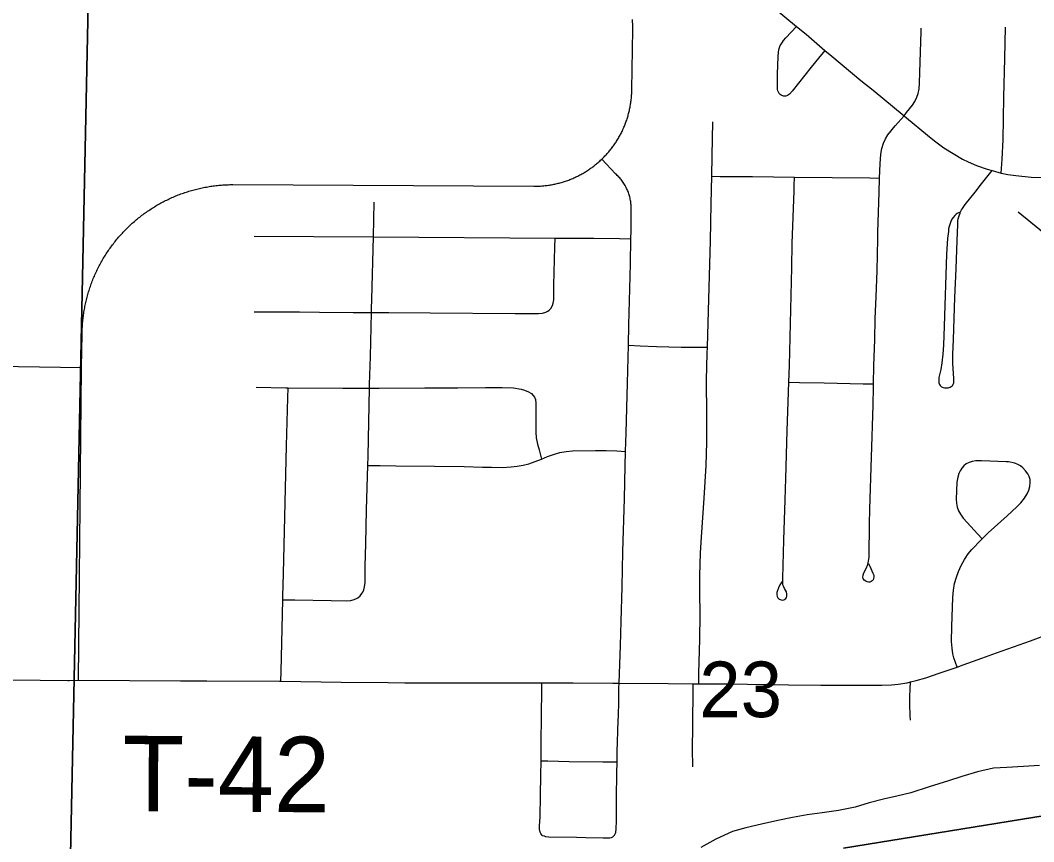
# Model space of a CAD drawing. Extents: x 0 to 34, y 0 to 22.
# Drawn here: x 5.405 to 6.168, y 18.807 to 19.426 of the extents above; entities that cross this region are included whole.
import ezdxf

# ---------------------------------------------------------------- set-up
doc = ezdxf.new("R2010")
doc.units = 0
for name, color, linetype in [('GM_X_City_Street', 7, 'Continuous'), ('GM_X_Major_River', 7, 'Continuous'), ('GM_X_Section', 7, 'Continuous'), ('GM_X_Section_Text', 7, 'Continuous'), ('GM_X_State_Route', 7, 'Continuous'), ('GM_X_Township_Road', 7, 'Continuous'), ('GM_X_Township_Road_Text', 7, 'Continuous')]:
    doc.layers.add(name, color=color, linetype=linetype)

msp = doc.modelspace()

# ---------------------------------------------------------------- linework, layer by layer
at = {"layer": 'GM_X_City_Street'}
msp.add_line((5.31011, 19.16656), (5.45108, 19.16403), dxfattribs=at)
for points in [[(5.4489, 18.92849), (5.45108, 19.16403), (5.45162, 19.18919), (5.45164, 19.19024), (5.45166, 19.19128), (5.4517, 19.19233), (5.45174, 19.19338), (5.4518, 19.19443), (5.45186, 19.19548), (5.45194, 19.19652), (5.45202, 19.19757), (5.45211, 19.19861), (5.45221, 19.19965), (5.45233, 19.2007), (5.45244, 19.20174), (5.45258, 19.20278), (5.45272, 19.20382), (5.45287, 19.20485), (5.45303, 19.20589), (5.4532, 19.20692), (5.45338, 19.20796), (5.45356, 19.20899), (5.45376, 19.21002), (5.45397, 19.21105), (5.45419, 19.21208), (5.45441, 19.2131), (5.45465, 19.21412), (5.45489, 19.21514), (5.45515, 19.21616), (5.45541, 19.21717), (5.45569, 19.21818), (5.45597, 19.21919), (5.45626, 19.2202), (5.45656, 19.2212), (5.45687, 19.2222), (5.45719, 19.2232), (5.45752, 19.2242), (5.45786, 19.22519), (5.4582, 19.22618), (5.45857, 19.22717), (5.45893, 19.22815), (5.4593, 19.22913), (5.45968, 19.23011), (5.46008, 19.23108), (5.46048, 19.23205), (5.46089, 19.23301), (5.46131, 19.23397), (5.46173, 19.23493), (5.46217, 19.23589), (5.46262, 19.23683), (5.46307, 19.23778), (5.46354, 19.23872), (5.464, 19.23966), (5.46449, 19.24059), (5.46497, 19.24152), (5.46547, 19.24244), (5.46598, 19.24335), (5.46649, 19.24427), (5.46701, 19.24518), (5.46754, 19.24608), (5.46808, 19.24698), (5.46863, 19.24788), (5.46918, 19.24877), (5.46975, 19.24965), (5.47032, 19.25053), (5.4709, 19.2514), (5.47149, 19.25227), (5.47209, 19.25314), (5.47269, 19.25399), (5.4733, 19.25484), (5.47392, 19.25569), (5.47455, 19.25653), (5.47518, 19.25737), (5.47582, 19.25819), (5.47647, 19.25901), (5.47713, 19.25983), (5.4778, 19.26064), (5.47847, 19.26145), (5.47915, 19.26224), (5.47983, 19.26303), (5.48053, 19.26382), (5.48123, 19.2646), (5.48194, 19.26537), (5.48266, 19.26614), (5.48338, 19.2669), (5.48411, 19.26765), (5.48485, 19.2684), (5.48559, 19.26914), (5.48634, 19.26987), (5.4871, 19.2706), (5.48786, 19.27131), (5.48863, 19.27202), (5.48941, 19.27273), (5.49019, 19.27342), (5.49098, 19.27411), (5.49178, 19.2748), (5.49258, 19.27547), (5.49339, 19.27614), (5.49421, 19.2768), (5.49503, 19.27745), (5.49585, 19.2781), (5.49669, 19.27874), (5.49753, 19.27936), (5.49836, 19.27998), (5.49922, 19.2806), (5.50007, 19.2812), (5.50093, 19.28181), (5.5018, 19.2824), (5.50267, 19.28297), (5.50355, 19.28355), (5.50443, 19.28412), (5.50532, 19.28468), (5.50621, 19.28522), (5.50711, 19.28576), (5.50801, 19.2863), (5.50892, 19.28683), (5.50983, 19.28734), (5.51075, 19.28785), (5.51167, 19.28835), (5.5126, 19.28884), (5.51353, 19.28932), (5.51446, 19.2898), (5.5154, 19.29026), (5.51635, 19.29072), (5.51729, 19.29117), (5.51825, 19.2916), (5.5192, 19.29203), (5.52016, 19.29246), (5.52112, 19.29287), (5.52209, 19.29328), (5.52306, 19.29367), (5.52404, 19.29406), (5.52501, 19.29443), (5.526, 19.2948), (5.52698, 19.29516), (5.52797, 19.29551), (5.52897, 19.29585), (5.52996, 19.29618), (5.53095, 19.29651), (5.53196, 19.29682), (5.53296, 19.29712), (5.53397, 19.29741), (5.53497, 19.2977), (5.53599, 19.29798), (5.537, 19.29825), (5.53802, 19.2985), (5.53904, 19.29875), (5.54006, 19.29899), (5.54108, 19.29922), (5.5421, 19.29944), (5.54313, 19.29965), (5.54416, 19.29985), (5.54519, 19.30004), (5.54622, 19.30022), (5.54726, 19.3004), (5.5483, 19.30056), (5.54933, 19.30071), (5.55037, 19.30086), (5.55141, 19.30099), (5.55245, 19.30112), (5.55349, 19.30123), (5.55454, 19.30133), (5.55558, 19.30143), (5.55662, 19.30152), (5.55767, 19.3016), (5.55872, 19.30166), (5.55976, 19.30172), (5.56081, 19.30177), (5.56186, 19.30181), (5.56291, 19.30183), (5.56396, 19.30185), (5.56501, 19.30186), (5.79187, 19.30063), (5.79271, 19.30063), (5.79355, 19.30065), (5.79438, 19.30066), (5.79522, 19.30069), (5.79605, 19.30073), (5.79688, 19.30078), (5.79772, 19.30084), (5.79855, 19.30091), (5.79939, 19.30098), (5.80022, 19.30107), (5.80105, 19.30116), (5.80188, 19.30127), (5.8027, 19.30138), (5.80353, 19.3015), (5.80436, 19.30164), (5.80518, 19.30178), (5.806, 19.30193), (5.80682, 19.30209), (5.80764, 19.30227), (5.80846, 19.30245), (5.80927, 19.30263), (5.81009, 19.30283), (5.81089, 19.30304), (5.8117, 19.30326), (5.8125, 19.30348), (5.81331, 19.30372), (5.81411, 19.30397), (5.8149, 19.30422), (5.8157, 19.30449), (5.81649, 19.30475), (5.81728, 19.30504), (5.81806, 19.30532), (5.81884, 19.30563), (5.81962, 19.30593), (5.82039, 19.30625), (5.82116, 19.30657), (5.82193, 19.30691), (5.82269, 19.30725), (5.82345, 19.3076), (5.8242, 19.30796), (5.82496, 19.30833), (5.8257, 19.30871), (5.82644, 19.3091), (5.82718, 19.30949), (5.82791, 19.30989), (5.82864, 19.31031), (5.82936, 19.31072), (5.83008, 19.31115), (5.8308, 19.31159), (5.83151, 19.31203), (5.83221, 19.31248), (5.8329, 19.31294), (5.8336, 19.31341), (5.83428, 19.31389), (5.83497, 19.31437), (5.83564, 19.31486), (5.83631, 19.31536), (5.83698, 19.31587), (5.83764, 19.31638), (5.83829, 19.31691), (5.83894, 19.31743), (5.83958, 19.31797), (5.84022, 19.31852), (5.84084, 19.31906), (5.84147, 19.31962), (5.84208, 19.32019), (5.84299, 19.32105), (5.8436, 19.32164), (5.84419, 19.32223), (5.84478, 19.32282), (5.84536, 19.32342), (5.84593, 19.32404), (5.84651, 19.32465), (5.84706, 19.32528), (5.84762, 19.32591), (5.84816, 19.32654), (5.8487, 19.32719), (5.84923, 19.32784), (5.84975, 19.3285), (5.85027, 19.32915), (5.85078, 19.32982), (5.85128, 19.3305), (5.85177, 19.33117), (5.85226, 19.33186), (5.85274, 19.33255), (5.85321, 19.33324), (5.85367, 19.33394), (5.85412, 19.33465), (5.85457, 19.33535), (5.85501, 19.33608), (5.85543, 19.33679), (5.85586, 19.33752), (5.85627, 19.33825), (5.85667, 19.33898), (5.85707, 19.33972), (5.85745, 19.34047), (5.85783, 19.34121), (5.85821, 19.34197), (5.85857, 19.34272), (5.85892, 19.34349), (5.85926, 19.34425), (5.8596, 19.34502), (5.85993, 19.34579), (5.86024, 19.34657), (5.86055, 19.34735), (5.86085, 19.34813), (5.86114, 19.34892), (5.86142, 19.34971), (5.8617, 19.3505), (5.86196, 19.3513), (5.86221, 19.35209), (5.86246, 19.3529), (5.8627, 19.3537), (5.86292, 19.35451), (5.86314, 19.35532), (5.86335, 19.35613), (5.86355, 19.35695), (5.86374, 19.35777), (5.86392, 19.35858), (5.86409, 19.35941), (5.86425, 19.36023), (5.86441, 19.36105), (5.86455, 19.36188), (5.86468, 19.36271), (5.8648, 19.36354), (5.86492, 19.36437), (5.86502, 19.3652), (5.86512, 19.36603), (5.8652, 19.36687), (5.86528, 19.3677), (5.86534, 19.36854), (5.8654, 19.36937), (5.86545, 19.37021), (5.86549, 19.37105), (5.86552, 19.37189), (5.86554, 19.37273), (5.86554, 19.37357), (5.86621, 19.41858), (5.86622, 19.41969), (5.86622, 19.4208), (5.86621, 19.42191), (5.8662, 19.42301), (5.86617, 19.42412), (5.86613, 19.42523), (5.86608, 19.42634)], [(6.01096, 19.40293), (6.00617, 19.39713), (6.00062, 19.39039), (5.98638, 19.37223), (5.98424, 19.36996), (5.98353, 19.3694), (5.9827, 19.36892), (5.98152, 19.36845), (5.9803, 19.36838), (5.97966, 19.36845), (5.97796, 19.36917), (5.97715, 19.36976), (5.97655, 19.37039), (5.97617, 19.37092), (5.9754, 19.37258), (5.97522, 19.37346), (5.97514, 19.37442), (5.97533, 19.38526), (5.97578, 19.39811), (5.97602, 19.40188), (5.97618, 19.40307), (5.97644, 19.40428), (5.97676, 19.40525), (5.97734, 19.4066), (5.97799, 19.40776), (5.97896, 19.40927), (5.97988, 19.41052), (5.98152, 19.41237), (5.98564, 19.41669), (5.98953, 19.42104)], [(6.07055, 19.35366), (6.07245, 19.35607), (6.07683, 19.36161), (6.07869, 19.36437), (6.08026, 19.36764), (6.08121, 19.37046), (6.0819, 19.37399), (6.08218, 19.37823), (6.08243, 19.38628), (6.08337, 19.4173), (6.08343, 19.41977)], [(6.14357, 19.31043), (6.14445, 19.32106), (6.1451, 19.33568), (6.14573, 19.36762), (6.14644, 19.39683), (6.14702, 19.42048)], [(6.04386, 19.01636), (6.04489, 19.0145), (6.04712, 19.00919), (6.04772, 19.00765), (6.04785, 19.00609), (6.04763, 19.0051), (6.0472, 19.00421), (6.04655, 19.00346), (6.04572, 19.00289), (6.04479, 19.00254), (6.04382, 19.00245), (6.04283, 19.00262), (6.04187, 19.00305), (6.04063, 19.004), (6.03986, 19.00523), (6.03963, 19.00622), (6.03972, 19.00777), (6.04023, 19.00938), (6.04191, 19.01264), (6.04321, 19.0156), (6.04389, 19.01813), (6.04424, 19.02134), (6.04436, 19.02948), (6.04449, 19.03876), (6.04459, 19.04623), (6.04483, 19.0574), (6.04742, 19.13563), (6.04754, 19.14932), (6.04759, 19.15169), (6.04784, 19.16544), (6.04858, 19.18529), (6.04892, 19.20082), (6.04961, 19.21757), (6.0502, 19.23683), (6.05077, 19.26105), (6.05093, 19.26352), (6.05087, 19.26601), (6.05169, 19.29583), (6.052, 19.30682), (6.05249, 19.31752), (6.05304, 19.32487), (6.05381, 19.32905), (6.05502, 19.3331), (6.05647, 19.33638), (6.0584, 19.33942), (6.06379, 19.34614), (6.07055, 19.35366)], [(5.91594, 18.92586), (5.91612, 18.93383), (5.91673, 18.95932), (5.91696, 18.97798), (5.91673, 18.99477), (5.91672, 19.00721), (5.9172, 19.02461), (5.91794, 19.0364), (5.92005, 19.06556), (5.92162, 19.09039), (5.92207, 19.10779), (5.92193, 19.12831), (5.92185, 19.15444), (5.92236, 19.17496), (5.92249, 19.17936), (5.92334, 19.20666), (5.92482, 19.2595), (5.92527, 19.28748), (5.92572, 19.30813), (5.92607, 19.32355), (5.92667, 19.34904)], [(5.86492, 19.26101), (5.86508, 19.26736), (5.86509, 19.28398), (5.86508, 19.28484), (5.86505, 19.28571), (5.865, 19.28657), (5.86492, 19.28743), (5.86482, 19.28829), (5.86471, 19.28915), (5.86457, 19.29), (5.86441, 19.29085), (5.86423, 19.29169), (5.86403, 19.29254), (5.8638, 19.29337), (5.86356, 19.2942), (5.86329, 19.29502), (5.86301, 19.29584), (5.8627, 19.29664), (5.86238, 19.29745), (5.86203, 19.29823), (5.86167, 19.29902), (5.86129, 19.29979), (5.86088, 19.30056), (5.86046, 19.30131), (5.86002, 19.30206), (5.85956, 19.30279), (5.85908, 19.3035), (5.85858, 19.30421), (5.85807, 19.30491), (5.85755, 19.30559), (5.857, 19.30626), (5.85643, 19.30691), (5.85586, 19.30755), (5.85526, 19.30818), (5.85465, 19.30879), (5.85402, 19.30939), (5.85338, 19.30997), (5.84299, 19.32105)], [(5.92572, 19.30813), (5.93215, 19.30808), (5.95639, 19.3079), (5.98807, 19.30754), (6.04473, 19.3069), (6.052, 19.30682)], [(5.97878, 19.00302), (5.97706, 19.00039), (5.97595, 18.99821), (5.97484, 18.99474), (5.97472, 18.9931), (5.97503, 18.99158), (5.9755, 18.9907), (5.9766, 18.98966), (5.978, 18.98905), (5.979, 18.98894), (5.97996, 18.98908), (5.98084, 18.9895), (5.98157, 18.99015), (5.98208, 18.99096), (5.98237, 18.99192), (5.98239, 18.99348), (5.98196, 18.99506), (5.98053, 18.99767), (5.97969, 18.99951), (5.9794, 19.00047), (5.97925, 19.00152), (5.97918, 19.00538), (5.98001, 19.03395), (5.9811, 19.06437), (5.98163, 19.08049), (5.98257, 19.11649), (5.9833, 19.13822), (5.98377, 19.15299), (5.98417, 19.16553), (5.98606, 19.23943), (5.98637, 19.25745), (5.98771, 19.2972), (5.98784, 19.30092), (5.98807, 19.30754)], [(6.11277, 19.28117), (6.11112, 19.28046), (6.11046, 19.28013), (6.1098, 19.27968), (6.10927, 19.27918), (6.10873, 19.27863), (6.10751, 19.27709), (6.1066, 19.27573), (6.10582, 19.27417), (6.10517, 19.27261), (6.10453, 19.2704), (6.10414, 19.26853), (6.1039, 19.26664), (6.10328, 19.26121), (6.10258, 19.24941), (6.10069, 19.19531), (6.10026, 19.18103), (6.09985, 19.17411), (6.09912, 19.16753), (6.09822, 19.16268), (6.09715, 19.15853), (6.09678, 19.15647), (6.09666, 19.15437), (6.0967, 19.15347), (6.09682, 19.15264), (6.09703, 19.15186), (6.09732, 19.15124), (6.09769, 19.15058), (6.09818, 19.15005), (6.0988, 19.1496), (6.09942, 19.14927), (6.10007, 19.14902), (6.1009, 19.14886), (6.10176, 19.14878), (6.10271, 19.14878), (6.10373, 19.14891), (6.1046, 19.14911), (6.10534, 19.14936), (6.10604, 19.14969), (6.1067, 19.15018), (6.10723, 19.15084), (6.10764, 19.15158), (6.10793, 19.15244), (6.10809, 19.15343), (6.10809, 19.15459), (6.10801, 19.15586), (6.10778, 19.15961), (6.10738, 19.16704), (6.10731, 19.1739), (6.1078, 19.18508), (6.10876, 19.21677), (6.10967, 19.23852), (6.11048, 19.25965), (6.11094, 19.27145), (6.111, 19.27319), (6.11113, 19.27471), (6.11133, 19.27614), (6.1117, 19.27763), (6.11219, 19.27911), (6.11272, 19.28046), (6.1131, 19.28125), (6.11384, 19.28277), (6.11448, 19.28387), (6.11666, 19.28689), (6.12403, 19.2961), (6.12895, 19.30235), (6.13685, 19.31237)], [(5.60277, 18.98921), (5.61058, 18.98923), (5.61182, 18.98923), (5.63918, 18.98861), (5.651, 18.98841), (5.6541, 18.98865), (5.65651, 18.98924), (5.65819, 18.99003), (5.65929, 18.99063), (5.66104, 18.99214), (5.66236, 18.99391), (5.66303, 18.99487), (5.66375, 18.99655), (5.66436, 18.99897), (5.66467, 19.00206), (5.66487, 19.0145), (5.66529, 19.03129), (5.66578, 19.05679), (5.66675, 19.09024), (5.66695, 19.09721), (5.66801, 19.14861), (5.66807, 19.15129), (5.66869, 19.17244), (5.66955, 19.2056), (5.66963, 19.20848), (5.66969, 19.21524), (5.67102, 19.26246), (5.67162, 19.28875)], [(6.39816, 19.0822), (6.39659, 19.08212), (6.39588, 19.08219), (6.39518, 19.08235), (6.39276, 19.08406), (6.3907, 19.08537), (6.38203, 19.09265), (6.36815, 19.10416), (6.34448, 19.12431), (6.3296, 19.13685), (6.32166, 19.14353), (6.29403, 19.16667), (6.2758, 19.18171), (6.26781, 19.1884), (6.23529, 19.21562), (6.23182, 19.21846), (6.22821, 19.22141), (6.21651, 19.23096), (6.2064, 19.23935), (6.18492, 19.25716), (6.1727, 19.26773), (6.15638, 19.28112)], [(5.58107, 19.26312), (5.67102, 19.26246), (5.80786, 19.2616), (5.83694, 19.26151), (5.85629, 19.26116), (5.86492, 19.26101)], [(5.58119, 19.20591), (5.58182, 19.20592), (5.59302, 19.20598), (5.61541, 19.20594), (5.63034, 19.2058), (5.65585, 19.20563), (5.66955, 19.2056), (5.6826, 19.20558), (5.71371, 19.20529), (5.77779, 19.20476), (5.79522, 19.20481), (5.79832, 19.20511), (5.80072, 19.20576), (5.80239, 19.20657), (5.80339, 19.20727), (5.80469, 19.20859), (5.8059, 19.21075), (5.80643, 19.21252), (5.80676, 19.21498), (5.80689, 19.22622), (5.80767, 19.25483), (5.80786, 19.2616)], [(5.86297, 19.18084), (5.86332, 19.19621), (5.86417, 19.22328), (5.86448, 19.24251), (5.86492, 19.26101)], [(5.85251, 18.81185), (5.8534, 18.8139), (5.85384, 18.81658), (5.85392, 18.82273), (5.85414, 18.84033), (5.85437, 18.85826), (5.85448, 18.86702), (5.85461, 18.87485), (5.8546, 18.87611), (5.85482, 18.88095), (5.85501, 18.89135), (5.85542, 18.90284), (5.85571, 18.9112), (5.85573, 18.91737), (5.85589, 18.9229), (5.856, 18.92639), (5.85693, 18.9548), (5.85753, 18.9728), (5.85833, 18.99885), (5.85852, 19.01189), (5.8587, 19.02556), (5.85995, 19.0653), (5.86052, 19.09014), (5.86082, 19.10091), (5.86121, 19.11497), (5.86238, 19.15222), (5.86297, 19.18084)], [(5.86297, 19.18084), (5.87186, 19.1805), (5.88409, 19.18002), (5.90271, 19.17952), (5.91453, 19.17942), (5.92249, 19.17936)], [(5.58264, 19.14919), (5.60501, 19.14883), (5.60672, 19.14882), (5.6479, 19.14858), (5.66801, 19.14861), (5.67526, 19.14862), (5.70972, 19.14876), (5.73458, 19.14886), (5.75529, 19.14899), (5.76796, 19.14904), (5.77635, 19.14872), (5.78232, 19.1477), (5.78485, 19.1471), (5.78788, 19.14585), (5.78958, 19.14481), (5.79011, 19.1444), (5.79221, 19.14184), (5.79293, 19.13991), (5.79333, 19.13724), (5.79333, 19.12221), (5.7933, 19.1154), (5.79365, 19.11113), (5.79461, 19.10635), (5.79572, 19.10217), (5.79757, 19.09518)], [(5.60121, 18.92774), (5.6014, 18.93504), (5.60277, 18.98921), (5.60282, 18.99154), (5.60338, 19.00892), (5.60548, 19.10517), (5.60651, 19.14118), (5.60672, 19.14882)], [(5.98377, 19.15299), (5.99184, 19.15285), (6.01052, 19.15252), (6.03978, 19.15186), (6.04759, 19.15169)], [(5.66675, 19.09024), (5.67602, 19.09018), (5.68783, 19.09011), (5.71704, 19.08986), (5.7394, 19.08942), (5.75312, 19.08899), (5.75999, 19.08894), (5.76784, 19.08883), (5.77474, 19.08934), (5.77929, 19.0899), (5.78368, 19.09054), (5.78797, 19.09159), (5.79275, 19.09319), (5.79757, 19.09518), (5.80198, 19.097), (5.80658, 19.09869), (5.81129, 19.09997), (5.81609, 19.10086), (5.82096, 19.10131), (5.83831, 19.10157), (5.84636, 19.10161), (5.85438, 19.10122), (5.86082, 19.10091)], [(6.1106, 18.93848), (6.10934, 18.94203), (6.10816, 18.94536), (6.10731, 18.94856), (6.10666, 18.95276), (6.10631, 18.9578), (6.10647, 18.96903), (6.10723, 18.99079), (6.10775, 18.99643), (6.10862, 19.0014), (6.10993, 19.00628), (6.11144, 19.01043), (6.11353, 19.01503), (6.11599, 19.01945), (6.11883, 19.02363), (6.12164, 19.02706), (6.12862, 19.03424), (6.1294, 19.03501), (6.13394, 19.03949), (6.14829, 19.05244), (6.15558, 19.05915), (6.15861, 19.06221), (6.16131, 19.06574), (6.16322, 19.06894), (6.16443, 19.0717), (6.16521, 19.07452), (6.16553, 19.07738), (6.1654, 19.07969), (6.16481, 19.08194), (6.16381, 19.08399), (6.16207, 19.08636), (6.16, 19.08855), (6.15817, 19.09002), (6.15615, 19.09116), (6.15395, 19.09197), (6.14924, 19.09296), (6.14746, 19.09316), (6.12894, 19.09387), (6.12468, 19.09372), (6.12173, 19.09325), (6.1195, 19.09255), (6.11745, 19.09149), (6.11564, 19.09006), (6.11406, 19.08834), (6.11279, 19.08638), (6.11181, 19.08425), (6.11097, 19.08139), (6.11042, 19.07782), (6.10985, 19.06486), (6.11003, 19.06186), (6.11059, 19.05894), (6.11156, 19.05616), (6.11298, 19.05355), (6.11513, 19.05064), (6.12094, 19.04424), (6.12597, 19.03875), (6.1294, 19.03501)], [(5.79803, 18.81172), (5.79704, 18.81306), (5.79651, 18.81421), (5.79615, 18.81636), (5.79614, 18.81885), (5.79643, 18.82545), (5.7968, 18.84193), (5.79714, 18.85689), (5.79739, 18.86787), (5.79736, 18.86955), (5.7972, 18.88321), (5.79746, 18.89984), (5.79783, 18.92368), (5.79788, 18.92655)], [(5.91142, 18.86329), (5.91146, 18.86702), (5.91131, 18.87323), (5.91157, 18.89749), (5.91166, 18.91925), (5.91169, 18.9259)], [(6.07547, 18.89836), (6.07525, 18.90204), (6.07498, 18.91063), (6.075, 18.91612), (6.07519, 18.92214), (6.07536, 18.92725)], [(5.79739, 18.86787), (5.80241, 18.86777), (5.81844, 18.86746), (5.84366, 18.86698), (5.84797, 18.867), (5.85448, 18.86702)], [(5.79803, 18.81172), (5.79945, 18.81127), (5.80061, 18.81092), (5.80284, 18.81071), (5.82397, 18.81025), (5.83082, 18.81007), (5.84403, 18.80991), (5.84894, 18.80984), (5.85028, 18.81015), (5.8512, 18.81066), (5.85251, 18.81185)]]:
    msp.add_lwpolyline(points, dxfattribs=at)
at = {"layer": 'GM_X_Major_River'}
msp.add_lwpolyline([(6.17255, 18.8644), (6.16039, 18.86358), (6.14786, 18.86276), (6.13799, 18.86226), (6.12578, 18.85954), (6.11394, 18.85604), (6.104, 18.85288), (6.08947, 18.84832), (6.07569, 18.84374), (6.06501, 18.84135), (6.05509, 18.83895), (6.0444, 18.83619), (6.0337, 18.83305), (6.02112, 18.83034), (6.00895, 18.82875), (5.99753, 18.82715), (5.98648, 18.82515), (5.97542, 18.82278), (5.96322, 18.82006), (5.95139, 18.81732), (5.94146, 18.81454), (5.92879, 18.80879), (5.91763, 18.80263)], dxfattribs=at)
at = {"layer": 'GM_X_Section'}
for points in [[(4.46097, 19.44139), (5.4561, 19.43741), (5.43503, 18.42215), (4.43788, 18.43754)], [(5.4561, 19.43741), (6.46596, 19.43025), (6.44087, 18.40636), (5.43503, 18.42215)]]:
    msp.add_lwpolyline(points, close=True, dxfattribs=at)
at = {"layer": 'GM_X_State_Route'}
for p, q in [((5.95979, 19.44584), (5.98953, 19.42104)), ((6.13685, 19.31237), (6.14357, 19.31043))]:
    msp.add_line(p, q, dxfattribs=at)
for points in [[(5.98953, 19.42104), (5.99672, 19.41506), (6.01096, 19.40293)], [(6.01096, 19.40293), (6.01609, 19.39856), (6.03799, 19.38025), (6.04724, 19.3729), (6.07055, 19.35366)], [(6.07055, 19.35366), (6.07235, 19.35218), (6.08826, 19.33921)], [(6.08826, 19.33921), (6.09356, 19.33489), (6.10058, 19.32964), (6.11468, 19.32098), (6.11871, 19.31892), (6.12521, 19.31621), (6.13322, 19.31338), (6.13685, 19.31237)], [(6.14357, 19.31043), (6.14874, 19.30957), (6.15474, 19.30867), (6.16622, 19.30758), (6.1762, 19.30718), (6.18927, 19.30728), (6.2077, 19.3074)]]:
    msp.add_lwpolyline(points, dxfattribs=at)
at = {"layer": 'GM_X_Township_Road'}
msp.add_line((5.91169, 18.9259), (5.91594, 18.92586), dxfattribs=at)
for points in [[(6.1106, 18.93848), (6.11514, 18.94003), (6.12915, 18.94517), (6.14026, 18.94913), (6.16583, 18.95825), (6.17587, 18.96195), (6.19218, 18.9677), (6.19539, 18.96859)], [(6.07536, 18.92725), (6.07969, 18.92825), (6.08689, 18.93034), (6.0969, 18.93379), (6.1106, 18.93848)], [(5.34511, 18.92928), (5.3669, 18.92905), (5.39954, 18.92879), (5.42009, 18.92872), (5.44091, 18.92842)], [(5.44091, 18.92842), (5.44191, 18.9284), (5.4489, 18.92849)], [(5.4489, 18.92849), (5.52562, 18.92798), (5.54551, 18.928), (5.60019, 18.92775), (5.60121, 18.92774)], [(5.60121, 18.92774), (5.64677, 18.92707), (5.68217, 18.92679), (5.69458, 18.9267), (5.707, 18.9267), (5.72337, 18.9267)], [(5.72337, 18.9267), (5.73009, 18.92664), (5.74626, 18.92669), (5.7624, 18.92665), (5.79099, 18.92654), (5.79788, 18.92655)], [(5.79788, 18.92655), (5.82143, 18.92659), (5.85126, 18.92643), (5.856, 18.92639)], [(5.856, 18.92639), (5.89288, 18.92611), (5.91169, 18.9259)], [(5.91594, 18.92586), (5.91836, 18.92583), (5.937, 18.92572), (5.98358, 18.92519), (6.00781, 18.92493), (6.03077, 18.92487), (6.04253, 18.92486), (6.05371, 18.92492), (6.06118, 18.92515), (6.06617, 18.92566), (6.07298, 18.9267), (6.07536, 18.92725)], [(6.02505, 18.80214), (6.20324, 18.83103), (6.4444, 18.86381), (6.80642, 18.77572)], [(6.80642, 18.77572), (6.4444, 18.86381), (6.20324, 18.83103), (6.02505, 18.80214)]]:
    msp.add_lwpolyline(points, dxfattribs=at)

# ---------------------------------------------------------------- texts
at = {"layer": 'GM_X_Section_Text'}
msp.add_text('23', height=0.041856, rotation=0.00001, dxfattribs=at).set_placement((5.91639, 18.90073))
at = {"layer": 'GM_X_Township_Road_Text'}
msp.add_text('T-42', height=0.056818, rotation=359.64671, dxfattribs=at).set_placement((5.48196, 18.82997))

doc.saveas('drawing.dxf')
